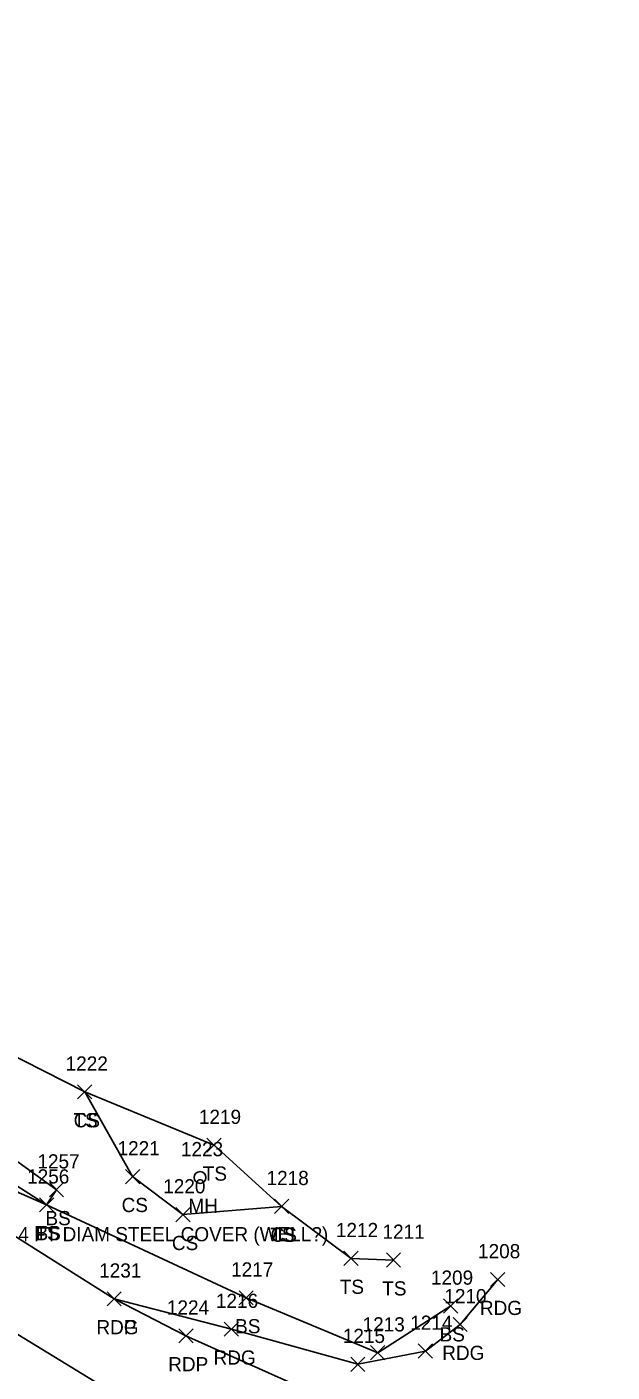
# Model space of a CAD drawing. Extents: x 1401404 to 1403982, y 557481 to 559873.
# Drawn here: x 1403271.2 to 1403353.7, y 558637.9 to 558827.6 of the extents above; entities that cross this region are included whole.
import ezdxf

# ---------------------------------------------------------------- set-up
doc = ezdxf.new("R2010")
doc.units = 0
for name, color, linetype in [('L_A', 7, 'Continuous'), ('L_I', 7, 'Continuous'), ('L_TIC', 7, 'Continuous'), ('LELB', 7, 'Continuous'), ('P_A', 7, 'Continuous'), ('P_I', 7, 'Continuous'), ('P_TIC', 7, 'Continuous'), ('PET', 7, 'Continuous'), ('PEU', 7, 'Continuous'), ('PRC', 7, 'Continuous'), ('U_A', 7, 'Continuous'), ('U_C', 7, 'Continuous'), ('U_I', 7, 'Continuous'), ('UUMH', 7, 'Continuous')]:
    doc.layers.add(name, color=color, linetype=linetype)

msp = doc.modelspace()

# ---------------------------------------------------------------- linework, layer by layer
at = {"layer": 'L_TIC'}
for points in [[(1403278.38, 558676.44), (1403280.38, 558678.44)], [(1403280.38, 558676.44), (1403278.38, 558678.44)], [(1403278.38, 558676.44), (1403280.38, 558678.44)], [(1403280.38, 558676.44), (1403278.38, 558678.44)], [(1403296.61, 558668.92), (1403298.61, 558670.92)], [(1403298.61, 558668.92), (1403296.61, 558670.92)], [(1403285.14, 558664.49), (1403287.14, 558666.49)], [(1403287.14, 558664.49), (1403285.14, 558666.49)], [(1403274.4, 558662.64), (1403276.4, 558664.64)], [(1403276.4, 558662.64), (1403274.4, 558664.64)], [(1403273.01, 558660.52), (1403275.01, 558662.52)], [(1403275.01, 558660.52), (1403273.01, 558662.52)], [(1403273.01, 558660.52), (1403275.01, 558662.52)], [(1403275.01, 558660.52), (1403273.01, 558662.52)], [(1403273.01, 558660.52), (1403275.01, 558662.52)], [(1403275.01, 558660.52), (1403273.01, 558662.52)], [(1403306.14, 558660.3), (1403308.14, 558662.3)], [(1403308.14, 558660.3), (1403306.14, 558662.3)], [(1403306.14, 558660.3), (1403308.14, 558662.3)], [(1403308.14, 558660.3), (1403306.14, 558662.3)], [(1403292.23, 558659.13), (1403294.23, 558661.13)], [(1403294.23, 558659.13), (1403292.23, 558661.13)], [(1403315.93, 558652.96), (1403317.93, 558654.96)], [(1403317.93, 558652.96), (1403315.93, 558654.96)], [(1403321.92, 558652.73), (1403323.92, 558654.73)], [(1403323.92, 558652.73), (1403321.92, 558654.73)], [(1403301.15, 558647.4), (1403303.15, 558649.4)], [(1403303.15, 558647.4), (1403301.15, 558649.4)], [(1403329.98, 558646.25), (1403331.98, 558648.25)], [(1403331.98, 558646.25), (1403329.98, 558648.25)], [(1403319.69, 558639.66), (1403321.69, 558641.66)], [(1403321.69, 558639.66), (1403319.69, 558641.66)]]:
    msp.add_lwpolyline(points, dxfattribs=at)
at = {"layer": 'LELB'}
for points in [[(1403274.01, 558661.52), (1403275.4, 558663.64), (1403262.1, 558673.2), (1403240.71, 558692.98), (1403238.02, 558696.32), (1403228.06, 558701.88), (1403206.41, 558715.04), (1403170.23, 558742.97), (1403133.19, 558771.75), (1403094.93, 558802.64), (1403083.69, 558810.62), (1403082.17, 558826.69)], [(1403274.01, 558661.52), (1403260.47, 558670.14), (1403237.93, 558689.8), (1403236.56, 558692.65), (1403235.19, 558693.99), (1403226.37, 558700.51), (1403205.44, 558713.37), (1403168.7, 558741.03), (1403131.9, 558770.06), (1403093.4, 558800.92), (1403083.69, 558810.62)], [(1403274.01, 558661.52), (1403259.11, 558668.05), (1403235.32, 558685.62), (1403232.73, 558691.67), (1403222.73, 558697.61), (1403203.01, 558709.69), (1403165.84, 558738.03), (1403130.55, 558767.76), (1403091.61, 558799.16), (1403082.35, 558808.67)], [(1403322.92, 558653.73), (1403316.93, 558653.96), (1403307.14, 558661.3), (1403297.61, 558669.92), (1403279.38, 558677.44), (1403267.85, 558683.34)], [(1403307.14, 558661.3), (1403293.23, 558660.13), (1403286.14, 558665.49), (1403279.38, 558677.44)], [(1403302.15, 558648.4), (1403274.01, 558661.52)], [(1403330.98, 558647.25), (1403320.69, 558640.66), (1403302.15, 558648.4)]]:
    msp.add_lwpolyline(points, dxfattribs=at)
at = {"layer": 'P_TIC'}
for points in [[(1403336.61, 558649.98), (1403338.61, 558651.98)], [(1403338.61, 558649.98), (1403336.61, 558651.98)], [(1403282.54, 558647.26), (1403284.54, 558649.26)], [(1403284.54, 558647.26), (1403282.54, 558649.26)], [(1403282.54, 558647.26), (1403284.54, 558649.26)], [(1403284.54, 558647.26), (1403282.54, 558649.26)], [(1403331.31, 558643.64), (1403333.31, 558645.64)], [(1403333.31, 558643.64), (1403331.31, 558645.64)], [(1403292.66, 558642.04), (1403294.66, 558644.04)], [(1403294.66, 558642.04), (1403292.66, 558644.04)], [(1403299.06, 558642.98), (1403301.06, 558644.98)], [(1403301.06, 558642.98), (1403299.06, 558644.98)], [(1403326.41, 558639.89), (1403328.41, 558641.89)], [(1403328.41, 558639.89), (1403326.41, 558641.89)], [(1403316.9, 558638.03), (1403318.9, 558640.03)], [(1403318.9, 558638.03), (1403316.9, 558640.03)]]:
    msp.add_lwpolyline(points, dxfattribs=at)
at = {"layer": 'PET'}
msp.add_lwpolyline([(1403552.49, 558594.8), (1403524.49, 558596.02), (1403520.25, 558595.63), (1403487.06, 558596.83), (1403440.08, 558600.18), (1403395.05, 558605.77), (1403363.07, 558611.97), (1403293.66, 558643.04), (1403283.54, 558648.26), (1403256.86, 558665.1), (1403232.94, 558682.45), (1403201.28, 558707.26), (1403164.55, 558736.67), (1403129.25, 558765.78)], dxfattribs=at)
at = {"layer": 'PEU'}
msp.add_lwpolyline([(1403337.61, 558650.98), (1403332.31, 558644.64), (1403327.41, 558640.89), (1403317.9, 558639.03), (1403300.06, 558643.98), (1403283.54, 558648.26)], dxfattribs=at)
at = {"layer": 'PRC'}
msp.add_lwpolyline([(1403567.87, 558582.77), (1403521.72, 558584.55), (1403486.23, 558585.01), (1403438.97, 558588.43), (1403393.1, 558594.9), (1403360.83, 558602.71), (1403288.92, 558631.6), (1403250.3, 558655.21), (1403225.89, 558672.35), (1403193.37, 558698.04), (1403157.15, 558726.96), (1403121.95, 558757.26), (1403083.22, 558789.98), (1403051.1, 558815.94), (1403004.27, 558851.49), (1402960.21, 558880.82), (1402921.63, 558903.82), (1402881.32, 558926.06), (1402807.32, 558964.73), (1402770.83, 558983.44)], dxfattribs=at)
at = {"layer": 'UUMH'}
for p, q in [((1403295.64, 558665.37), (1403295.64, 558665.37)), ((1403296.47, 558665.37), (1403296.47, 558665.37))]:
    msp.add_line(p, q, dxfattribs=at)
msp.add_circle((1403295.64, 558665.37), 0.833, dxfattribs=at)

# ---------------------------------------------------------------- texts
at = {"layer": 'L_A'}
for s, p in [('TS', (1403277.79, 558672.44)), ('CS', (1403277.82, 558672.44)), ('TS', (1403296.02, 558664.92)), ('CS', (1403284.58, 558660.49)), ('BS', (1403273.84, 558658.64)), ('TS', (1403272.42, 558656.52)), ('BS', (1403272.45, 558656.52)), ('BS', (1403272.45, 558656.52)), ('CS', (1403291.67, 558655.13)), ('TS', (1403305.55, 558656.3)), ('CS', (1403305.58, 558656.3)), ('TS', (1403315.34, 558648.96)), ('TS', (1403321.33, 558648.73)), ('BS', (1403300.59, 558643.4)), ('BS', (1403329.42, 558642.25))]:
    msp.add_text(s, height=2, dxfattribs=at).set_placement(p)
at = {"layer": 'L_I'}
for s, p in [('1222', (1403276.69, 558680.44)), ('1222', (1403276.69, 558680.44)), ('1219', (1403295.48, 558672.92)), ('1221', (1403284.01, 558668.49)), ('1257', (1403272.71, 558666.64)), ('1256', (1403271.26, 558664.52)), ('1256', (1403271.26, 558664.52)), ('1256', (1403271.26, 558664.52)), ('1218', (1403305.02, 558664.3)), ('1218', (1403305.02, 558664.3)), ('1220', (1403290.45, 558663.13)), ('1212', (1403314.8, 558656.96)), ('1211', (1403321.37, 558656.73)), ('1217', (1403300.02, 558651.4)), ('1209', (1403328.2, 558650.25)), ('1213', (1403318.56, 558643.66))]:
    msp.add_text(s, height=2, dxfattribs=at).set_placement(p)
at = {"layer": 'P_A'}
for s, p in [('RDG', (1403335.1, 558645.98)), ('RDG', (1403281.03, 558643.26)), ('RDP', (1403281.03, 558643.26)), ('RDG', (1403329.79, 558639.64)), ('RDP', (1403291.15, 558638.04)), ('RDG', (1403297.55, 558638.98))]:
    msp.add_text(s, height=2, dxfattribs=at).set_placement(p)
at = {"layer": 'P_I'}
for s, p in [('1208', (1403334.84, 558653.98)), ('1231', (1403281.42, 558651.26)), ('1231', (1403281.42, 558651.26)), ('1216', (1403297.88, 558646.98)), ('1210', (1403330.09, 558647.64)), ('1224', (1403290.97, 558646.04)), ('1214', (1403325.28, 558643.89)), ('1215', (1403315.77, 558642.03))]:
    msp.add_text(s, height=2, dxfattribs=at).set_placement(p)
at = {"layer": 'U_A'}
msp.add_text('MH', height=2, dxfattribs=at).set_placement((1403294, 558660.37))
at = {"layer": 'U_C'}
msp.add_text('4 FT DIAM STEEL COVER (WELL?)', height=2, dxfattribs=at).set_placement((1403270.02, 558656.37))
at = {"layer": 'U_I'}
msp.add_text('1223', height=2, dxfattribs=at).set_placement((1403292.95, 558668.37))

doc.saveas('drawing.dxf')
